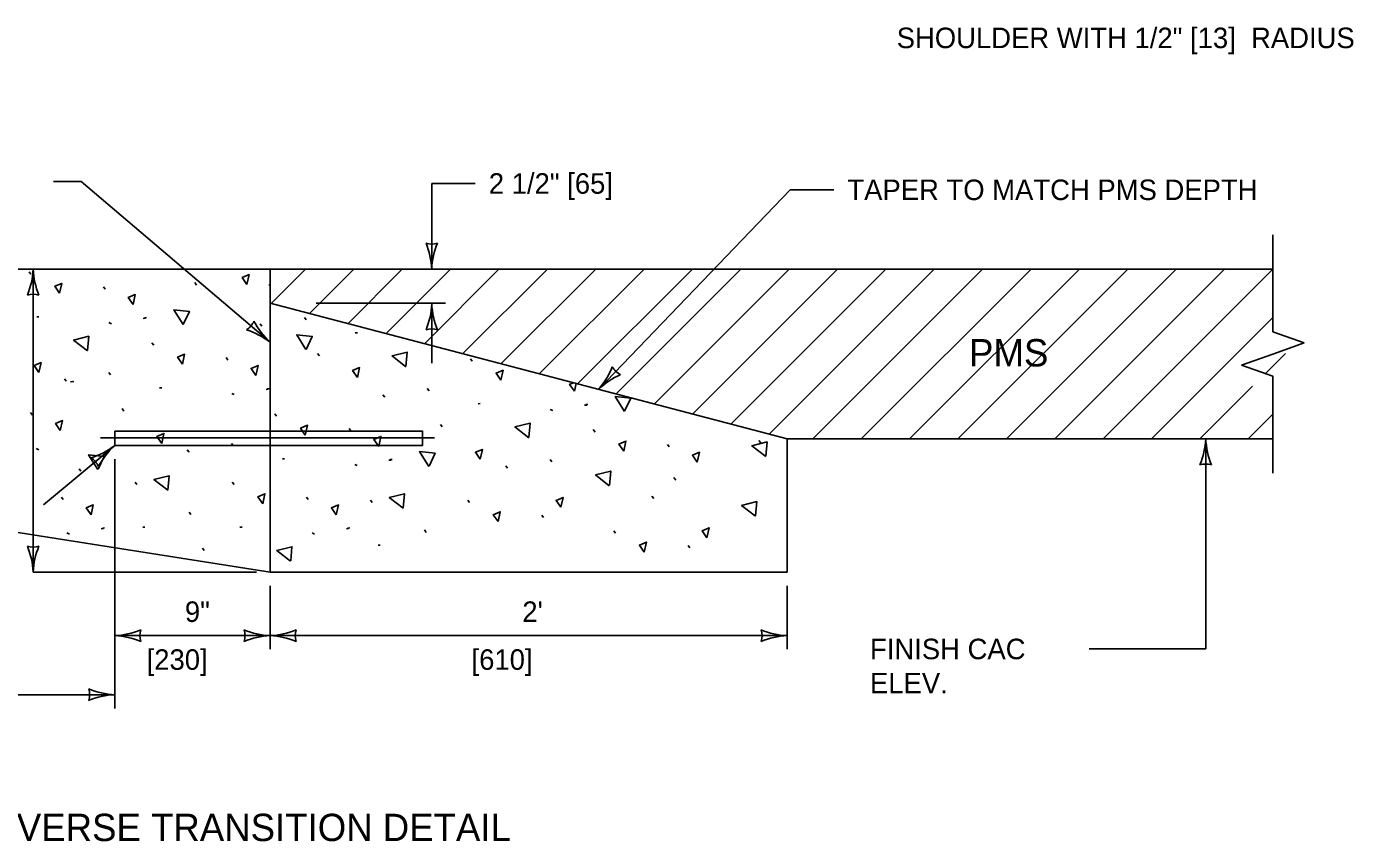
# Model space of a CAD drawing. Extents: x 49979.1 to 50021, y 49966.7 to 50011.4.
# Drawn here: x 50001.863 to 50005.742, y 49990.084 to 49992.467 of the extents above; entities that cross this region are included whole.
import ezdxf

# ---------------------------------------------------------------- set-up
doc = ezdxf.new("R2010")
doc.units = 0
for name, color, linetype in [('Level 1', 7, 'Continuous'), ('Level 13', 7, 'Continuous'), ('Level 2', 7, 'Continuous'), ('Level 3', 7, 'Continuous'), ('Level 5', 7, 'Continuous'), ('Level 6', 7, 'Continuous')]:
    doc.layers.add(name, color=color, linetype=linetype)

msp = doc.modelspace()

# ---------------------------------------------------------------- linework, layer by layer
at = {"layer": 'Level 1'}
for p, q in [((50005.5068, 49991.7578), (50000.7637, 49991.7578)), ((50005.5068, 49991.7578), (50000.7637, 49991.7578)), ((50002.5776, 49991.657), (50002.6783, 49991.7578)), ((50002.6896, 49991.6276), (50002.8198, 49991.7578)), ((50002.8017, 49991.5982), (50002.9612, 49991.7578)), ((50002.9137, 49991.5689), (50003.1026, 49991.7578)), ((50003.0258, 49991.5395), (50003.244, 49991.7578)), ((50003.1378, 49991.5101), (50003.3855, 49991.7578)), ((50003.2498, 49991.4807), (50003.5269, 49991.7578)), ((50003.3619, 49991.4514), (50003.6683, 49991.7578)), ((50003.4739, 49991.422), (50003.8097, 49991.7578)), ((50003.586, 49991.3926), (50003.9512, 49991.7578)), ((50003.698, 49991.3632), (50004.0926, 49991.7578)), ((50003.8101, 49991.3338), (50004.234, 49991.7578)), ((50003.9221, 49991.3045), (50004.3754, 49991.7578)), ((50004.0341, 49991.2751), (50004.5168, 49991.7578)), ((50004.1618, 49991.2613), (50004.6582, 49991.7578)), ((50004.3032, 49991.2613), (50004.7997, 49991.7578)), ((50004.4447, 49991.2613), (50004.9411, 49991.7578)), ((50004.5861, 49991.2613), (50005.0825, 49991.7578)), ((50004.7275, 49991.2613), (50005.224, 49991.7578)), ((50004.8689, 49991.2613), (50005.3654, 49991.7578)), ((50005.0104, 49991.2613), (50005.5068, 49991.7578)), ((50002.5747, 49991.6578), (50004.0865, 49991.2613)), ((50002.5747, 49991.6578), (50002.5747, 49990.8713)), ((50005.1518, 49991.2613), (50005.5068, 49991.6163)), ((50005.483, 49991.4511), (50005.5433, 49991.5114)), ((50005.2932, 49991.2613), (50005.4476, 49991.4157)), ((50005.4346, 49991.2613), (50005.5068, 49991.3335)), ((50004.0865, 49991.2613), (50004.0865, 49990.8713)), ((50004.0865, 49991.2613), (50005.5068, 49991.2613)), ((50000.7637, 49991.1578), (50002.5747, 49990.8713)), ((50002.5747, 49990.8713), (50004.0865, 49990.8713))]:
    msp.add_line(p, q, dxfattribs=at)
msp.add_lwpolyline([(50002.1204, 49991.2844), (50003.02, 49991.2844), (50003.02, 49991.242), (50002.1204, 49991.242)], close=True, dxfattribs=at)
at = {"layer": 'Level 13'}
for p, q in [((50001.8754, 49991.7427), (50001.8702, 49991.7498)), ((50002.3598, 49991.7112), (50002.3546, 49991.7183)), ((50002.0924, 49991.6994), (50002.0873, 49991.7065)), ((50001.8926, 49991.6179), (50001.899, 49991.6183)), ((50002.1036, 49991.6014), (50002.111, 49991.5982)), ((50002.2038, 49991.6136), (50002.2102, 49991.614)), ((50002.2073, 49991.6156), (50002.2137, 49991.616)), ((50002.5507, 49991.5907), (50002.5455, 49991.5978)), ((50002.6803, 49991.6092), (50002.6751, 49991.6163)), ((50002.8237, 49991.5715), (50002.8301, 49991.5719)), ((50002.2346, 49991.5353), (50002.2295, 49991.5423)), ((50002.4516, 49991.492), (50002.4465, 49991.4991)), ((50002.719, 49991.5038), (50002.7139, 49991.5109)), ((50003.1658, 49991.4888), (50003.1607, 49991.4959)), ((50002.1084, 49991.4482), (50002.1032, 49991.4553)), ((50003.3828, 49991.4456), (50003.3826, 49991.4459)), ((50001.9787, 49991.4297), (50001.9736, 49991.4368)), ((50001.9911, 49991.4283), (50001.9975, 49991.4287)), ((50001.9947, 49991.4284), (50002.0011, 49991.4288)), ((50002.2518, 49991.4105), (50002.2582, 49991.4109)), ((50002.5631, 49991.4062), (50002.5695, 49991.4066)), ((50002.5666, 49991.4082), (50002.573, 49991.4086)), ((50003.0395, 49991.4018), (50003.0344, 49991.4089)), ((50002.4629, 49991.394), (50002.4702, 49991.3908)), ((50002.9099, 49991.3833), (50002.9048, 49991.3904)), ((50003.183, 49991.3641), (50003.1894, 49991.3645)), ((50001.8797, 49991.3311), (50001.8746, 49991.3381)), ((50002.1471, 49991.3428), (50002.1419, 49991.3499)), ((50002.5939, 49991.3279), (50002.5887, 49991.3349)), ((50003.394, 49991.3476), (50003.4014, 49991.3444)), ((50003.4942, 49991.3597), (50003.5006, 49991.3601)), ((50003.4978, 49991.3618), (50003.5042, 49991.3622)), ((50002.8109, 49991.2846), (50002.8057, 49991.2917)), ((50003.0783, 49991.2964), (50003.0731, 49991.3034)), ((50003.525, 49991.2814), (50003.5199, 49991.2885)), ((50002.4676, 49991.2408), (50002.4624, 49991.2479)), ((50004.0094, 49991.2499), (50004.0043, 49991.257)), ((50001.8909, 49991.233), (50001.8983, 49991.2298)), ((50002.338, 49991.2223), (50002.3328, 49991.2294)), ((50003.7421, 49991.2382), (50003.7369, 49991.2453)), ((50002.0219, 49991.1669), (50002.0168, 49991.174)), ((50002.611, 49991.2031), (50002.6174, 49991.2035)), ((50002.8221, 49991.1866), (50002.8295, 49991.1834)), ((50002.9223, 49991.1988), (50002.9287, 49991.1992)), ((50002.9258, 49991.2008), (50002.9322, 49991.2012)), ((50003.2692, 49991.1759), (50003.264, 49991.183)), ((50003.3988, 49991.1944), (50003.3936, 49991.2015)), ((50002.1853, 49991.1275), (50002.1802, 49991.1346)), ((50002.4695, 49991.1275), (50002.4643, 49991.1346)), ((50003.7607, 49991.1409), (50003.7555, 49991.148)), ((50003.6964, 49991.0869), (50003.6913, 49991.0939)), ((50001.9697, 49991.0843), (50001.9645, 49991.0913)), ((50002.6865, 49991.0843), (50002.6814, 49991.0913)), ((50002.8734, 49991.0749), (50002.8683, 49991.082)), ((50003.1576, 49991.0749), (50003.1525, 49991.082)), ((50002.3432, 49991.0404), (50002.3381, 49991.0475)), ((50003.3746, 49991.0317), (50003.3695, 49991.0387)), ((50001.9809, 49990.9862), (50001.9883, 49990.983)), ((50002.0811, 49990.9984), (50002.0875, 49990.9988)), ((50002.0846, 49991.0004), (50002.091, 49991.0009)), ((50002.2025, 49991.0027), (50002.2089, 49991.0031)), ((50002.4867, 49991.0027), (50002.493, 49991.0031)), ((50002.6977, 49990.9862), (50002.7051, 49990.983)), ((50002.7979, 49990.9984), (50002.8043, 49990.9988)), ((50002.8014, 49991.0004), (50002.8078, 49991.0009)), ((50003.0313, 49990.9878), (50003.0262, 49990.9949)), ((50003.5849, 49990.9859), (50003.5797, 49990.9929)), ((50002.3819, 49990.935), (50002.3768, 49990.9421)), ((50002.8906, 49990.9501), (50002.897, 49990.9506)), ((50003.8019, 49990.9426), (50003.7968, 49990.9497))]:
    msp.add_line(p, q, dxfattribs=at)
for points in [[(50001.9592, 49991.6871), (50001.9453, 49991.7075), (50001.9657, 49991.7162), (50001.9592, 49991.6871)], [(50002.5071, 49991.7129), (50002.4932, 49991.7332), (50002.5136, 49991.7419), (50002.5071, 49991.7129)], [(50002.174, 49991.6544), (50002.1601, 49991.6747), (50002.1806, 49991.6834), (50002.174, 49991.6544)], [(50002.5747, 49991.7092), (50002.5722, 49991.7112), (50002.5747, 49991.7118)], [(50002.3206, 49991.5954), (50002.2934, 49991.6388), (50002.3388, 49991.6341), (50002.321, 49991.5961)], [(50002.0407, 49991.5187), (50002.0003, 49991.5502), (50002.0446, 49991.5613), (50002.0409, 49991.5196)], [(50002.6798, 49991.5223), (50002.6526, 49991.5657), (50002.6981, 49991.561), (50002.6803, 49991.5231)], [(50001.8988, 49991.4556), (50001.8849, 49991.4759), (50001.9053, 49991.4846), (50001.8988, 49991.4556)], [(50002.3184, 49991.4797), (50002.3045, 49991.5001), (50002.3249, 49991.5088), (50002.3184, 49991.4797)], [(50002.9719, 49991.4723), (50002.9314, 49991.5038), (50002.9758, 49991.5149), (50002.972, 49991.4732)], [(50002.5333, 49991.4469), (50002.5194, 49991.4673), (50002.5398, 49991.476), (50002.5333, 49991.4469)], [(50002.83, 49991.4408), (50002.8161, 49991.4612), (50002.8365, 49991.4699), (50002.83, 49991.4408)], [(50003.2496, 49991.4333), (50003.2357, 49991.4536), (50003.2561, 49991.4623), (50003.2496, 49991.4333)], [(50003.4645, 49991.4005), (50003.4506, 49991.4208), (50003.4611, 49991.4253)], [(50003.4695, 49991.4231), (50003.4645, 49991.4005)], [(50003.611, 49991.3415), (50003.5838, 49991.385), (50003.6292, 49991.3802), (50003.6114, 49991.3423)], [(50001.9614, 49991.286), (50001.9475, 49991.3063), (50001.9679, 49991.315), (50001.9614, 49991.286)], [(50002.6777, 49991.2723), (50002.6638, 49991.2926), (50002.6842, 49991.3014), (50002.6777, 49991.2723)], [(50003.3311, 49991.2649), (50003.2907, 49991.2963), (50003.335, 49991.3075), (50003.3313, 49991.2657)], [(50002.258, 49991.2482), (50002.2441, 49991.2685), (50002.2646, 49991.2772), (50002.258, 49991.2482)], [(50002.8925, 49991.2395), (50002.8786, 49991.2599), (50002.899, 49991.2686), (50002.8925, 49991.2395)], [(50003.6088, 49991.2259), (50003.5949, 49991.2462), (50003.6153, 49991.2549), (50003.6088, 49991.2259)], [(50004.0239, 49991.2098), (50003.9834, 49991.2413), (50004.0278, 49991.2524), (50004.024, 49991.2107)], [(50002.0713, 49991.1716), (50002.0441, 49991.2151), (50002.0895, 49991.2103), (50002.0717, 49991.1724)], [(50003.0391, 49991.1806), (50003.0118, 49991.224), (50003.0573, 49991.2193), (50003.0395, 49991.1813)], [(50003.1892, 49991.2018), (50003.1753, 49991.2221), (50003.1957, 49991.2308), (50003.1892, 49991.2018)], [(50003.8237, 49991.1931), (50003.8098, 49991.2134), (50003.8302, 49991.2222), (50003.8237, 49991.1931)], [(50002.2756, 49991.1109), (50002.2351, 49991.1424), (50002.2795, 49991.1535), (50002.2757, 49991.1118)], [(50003.5667, 49991.1244), (50003.5263, 49991.1558), (50003.5707, 49991.167), (50003.5669, 49991.1252)], [(50002.5533, 49991.0719), (50002.5394, 49991.0923), (50002.5598, 49991.101), (50002.5533, 49991.0719)], [(50002.9637, 49991.0583), (50002.9233, 49991.0898), (50002.9676, 49991.1009), (50002.9639, 49991.0592)], [(50002.0513, 49991.0392), (50002.0374, 49991.0595), (50002.0578, 49991.0682), (50002.0513, 49991.0392)], [(50002.7681, 49991.0392), (50002.7542, 49991.0595), (50002.7747, 49991.0682), (50002.7681, 49991.0392)], [(50003.4248, 49991.0612), (50003.4109, 49991.0816), (50003.4313, 49991.0903), (50003.4248, 49991.0612)], [(50003.994, 49991.0353), (50003.9536, 49991.0668), (50003.9979, 49991.0779), (50003.9942, 49991.0362)], [(50003.2414, 49991.0194), (50003.2275, 49991.0397), (50003.2479, 49991.0484), (50003.2414, 49991.0194)], [(50003.8521, 49990.9722), (50003.8382, 49990.9925), (50003.8586, 49991.0013), (50003.8521, 49990.9722)], [(50002.6348, 49990.9035), (50002.5944, 49990.935), (50002.6387, 49990.9461), (50002.635, 49990.9044)], [(50003.6687, 49990.9303), (50003.6548, 49990.9506), (50003.6752, 49990.9594), (50003.6687, 49990.9303)]]:
    msp.add_lwpolyline(points, dxfattribs=at)
at = {"layer": 'Level 3'}
for p, q in [((50001.942, 49992.014), (50002.022, 49992.014)), ((50002.5747, 49991.5439), (50002.022, 49992.014)), ((50003.0475, 49992.0083), (50003.0475, 49991.7578)), ((50003.0475, 49992.0083), (50003.1743, 49992.0083)), ((50003.5349, 49991.406), (50004.0959, 49991.9898)), ((50004.0959, 49991.9898), (50004.2227, 49991.9898)), ((50001.882, 49990.8713), (50001.882, 49991.7578)), ((50002.7094, 49991.6578), (50003.0876, 49991.6578)), ((50003.0475, 49991.6578), (50003.0475, 49991.4831)), ((50005.3105, 49991.2602), (50005.3105, 49990.647)), ((50002.1204, 49991.242), (50001.9127, 49991.0686)), ((50002.1204, 49991.202), (50002.1204, 49990.646)), ((50002.5347, 49990.8713), (50001.882, 49990.8713)), ((50002.5747, 49990.8313), (50002.5747, 49990.646)), ((50004.0865, 49990.646), (50004.0865, 49990.8313)), ((50002.1204, 49990.686), (50002.5747, 49990.686)), ((50002.5747, 49990.686), (50004.0865, 49990.686)), ((50002.1204, 49990.646), (50002.1204, 49990.4733)), ((50005.3105, 49990.647), (50004.9694, 49990.647)), ((50000.7653, 49990.5133), (50002.1204, 49990.5133)), ((50002.1204, 49990.4733), (50002.1204, 49990.5133))]:
    msp.add_line(p, q, dxfattribs=at)
for centre, radius, start, end in [((50003.0475, 49991.886), 0.0548, 252.1388, 287.8612), ((50002.8148, 49991.7463), 0.233, 2.8273, 22.0772), ((50003.2696, 49991.7486), 0.2223, 157.456, 177.6395), ((50001.6598, 49991.7669), 0.2223, 337.456, 357.6395), ((50002.1147, 49991.7693), 0.233, 182.8273, 202.0772), ((50001.882, 49991.6295), 0.0548, 72.1388, 107.8612), ((50002.8254, 49991.6657), 0.2223, 337.456, 357.6395), ((50003.2802, 49991.6681), 0.233, 182.8273, 202.0772), ((50002.477, 49991.627), 0.0548, 301.7572, 337.4796), ((50002.7256, 49991.7072), 0.2223, 207.0744, 227.2579), ((50002.4327, 49991.3592), 0.233, 52.4457, 71.6956), ((50003.0475, 49991.5284), 0.0548, 72.1388, 107.8612), ((50003.3591, 49991.559), 0.233, 318.9658, 338.2156), ((50003.6887, 49991.2455), 0.2223, 113.5945, 133.778), ((50003.6237, 49991.4984), 0.0548, 208.2773, 243.9997), ((50005.0883, 49991.2705), 0.2223, 337.456, 357.6395), ((50005.5432, 49991.2728), 0.233, 182.8273, 202.0772), ((50001.9851, 49991.4184), 0.2223, 287.3083, 307.4918), ((50002.2784, 49991.0707), 0.233, 132.6796, 151.9295), ((50002.022, 49991.1598), 0.0548, 21.9911, 57.7135), ((50005.3105, 49991.1331), 0.0548, 72.1388, 107.8612), ((50001.882, 49990.9996), 0.0548, 252.1388, 287.8612), ((50001.6493, 49990.8599), 0.233, 2.8273, 22.0772), ((50002.1041, 49990.8622), 0.2223, 157.456, 177.6395), ((50002.1089, 49990.9187), 0.233, 272.8273, 292.0772), ((50002.1113, 49990.4639), 0.2223, 67.456, 87.6395), ((50002.2486, 49990.686), 0.0548, 162.1388, 197.8612), ((50002.5839, 49990.9082), 0.2223, 247.456, 267.6395), ((50002.4465, 49990.686), 0.0548, 342.1388, 17.8612), ((50002.5862, 49990.4533), 0.233, 92.8273, 112.0772), ((50002.5632, 49990.9187), 0.233, 272.8273, 292.0772), ((50002.5655, 49990.4639), 0.2223, 67.456, 87.6395), ((50002.7029, 49990.686), 0.0548, 162.1388, 197.8612), ((50004.0957, 49990.9082), 0.2223, 247.456, 267.6395), ((50003.9583, 49990.686), 0.0548, 342.1388, 17.8612), ((50004.098, 49990.4533), 0.233, 92.8273, 112.0772), ((50002.1296, 49990.7354), 0.2223, 247.456, 267.6395), ((50001.9922, 49990.5133), 0.0548, 342.1388, 17.8612), ((50002.1319, 49990.2806), 0.233, 92.8273, 112.0772)]:
    msp.add_arc(centre, radius, start, end, dxfattribs=at)
at = {"layer": 'Level 5'}
msp.add_line((50003.056, 49991.2646), (50002.0787, 49991.2646), dxfattribs=at)
at = {"layer": 'Level 6'}
for p, q in [((50005.5068, 49991.8578), (50005.5068, 49991.5744)), ((50002.5747, 49991.7578), (50005.5068, 49991.7578)), ((50002.5747, 49991.7578), (50002.5747, 49991.6578)), ((50005.5982, 49991.542), (50005.5068, 49991.5744)), ((50005.5982, 49991.542), (50005.5068, 49991.5096)), ((50005.5068, 49991.5096), (50005.4154, 49991.4772)), ((50005.5068, 49991.4448), (50005.4154, 49991.4772)), ((50005.5068, 49991.4448), (50005.5067, 49991.1613))]:
    msp.add_line(p, q, dxfattribs=at)

# ---------------------------------------------------------------- texts
at = {"layer": 'Level 2'}
for s, height, p in [('SHOULDER WITH 1/2" [13]  RADIUS', 0.06, (50004.4069, 49992.4041)), ('PMS', 0.08, (50004.6185, 49991.4732)), ('PMS TRANSVERSE TRANSITION DETAIL', 0.08, (50001.2102, 49990.0851))]:
    msp.add_text(s, height=height, dxfattribs=at).set_placement(p)
for s, rotation, p in [('2 1/2" [65] ', 360, (50003.2143, 49991.9783)), ('TAPER TO MATCH PMS DEPTH', 360, (50004.2627, 49991.9598)), ('9"', 0, (50002.3257, 49990.726)), ("2'", 0, (50003.3123, 49990.726)), ('FINISH CAC', 360, (50004.3289, 49990.617)), ('[230]', 0, (50002.2138, 49990.586)), ('[610]', 0, (50003.1638, 49990.586)), ('ELEV.', 360, (50004.3289, 49990.517))]:
    msp.add_text(s, height=0.06, rotation=rotation, dxfattribs=at).set_placement(p)

doc.saveas('drawing.dxf')
